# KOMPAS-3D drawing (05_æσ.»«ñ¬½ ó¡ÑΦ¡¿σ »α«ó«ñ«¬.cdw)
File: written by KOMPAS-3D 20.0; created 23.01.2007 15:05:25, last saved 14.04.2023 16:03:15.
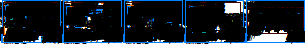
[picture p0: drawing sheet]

Sheets 1-5: A2, landscape

Document properties: Автор: Лескин; Организация: ЗАО ИТФ "СИСТЕМЫ И ТЕХНОЛОГИИ"; Разработал: Антошин; Проверил: Тарасов; Утвердил: Шмончев; Н. контр.: Силаков; Форматы листов документа: 5xA2; Полное имя файла: \\s-tech\depts\Отдел_ПКО\Проекты\Типовые проекты МКД 2023\!Типовой проект\1_Типовой проект МКД_RS-485\05_Сх.подкл внешних проводок.cdw

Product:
- Part/product: (unnamed)
  - Component: \\Helios\отдел_пко\Общая папка Компас\_Addons\Signatures\Signatures.lfr|Шмончев  | Полное имя файла: C:\Users\MAntoshin\AppData\Local\Temp\hsklda.frw; source file: \\s-tech\depts\Отдел_ПКО\Проекты\Program Files\ASCON\KOMPAS-3D V13\Libs\_Addons\Signatures\Signatures.lfr
  - Component: \\Helios\отдел_пко\Общая папка Компас\_Addons\Signatures\Signatures.lfr|Силаков  | Полное имя файла: C:\Users\MAntoshin\AppData\Local\Temp\eiczbt.frw; source file: \\s-tech\depts\Отдел_ПКО\Проекты\Program Files\ASCON\KOMPAS-3D V13\Libs\_Addons\Signatures\Signatures.lfr
  - Component: \\Helios\отдел_пко\Общая папка Компас\_Addons\Signatures\Signatures.lfr|Тарасов  | Полное имя файла: C:\Users\MAntoshin\AppData\Local\Temp\qlkzkl.frw; source file: \\s-tech\depts\Отдел_ПКО\Проекты\Program Files\ASCON\KOMPAS-3D V13\Libs\_Addons\Signatures\Signatures.lfr

Title block, sheet 1: designation: ВЛСТ 1277.01.002 С5; sheet number: 1; Количество листов документа: 3; organisation: АО ГК / "Системы и Технологии"; Форматы листов документа: A2; stored path: C:\Program Files\ASCON\KOMPAS-3D V8 Plus\Templates\Чертеж строительный зданий и сооружений.cdt; cell 302: Система учета электроэнергии (с организацией удаленного / сбора данных) потребителей; cell 303: Типовой проект ИСУЭ многоквартирного / дома с использованием проводного / канала связи RS-485; cell 304: Схема электрическая однолинейная; cell 320: Р
Title block, sheet 2: sheet number: 2; Форматы листов документа: A3; stored path: Z:\Проекты\ЭнергоКурган\СЭ_Схема однолинейная.cdw
Title block, sheet 3: sheet number: 3; Форматы листов документа: A4
Title block, sheet 4: sheet number: 4; stored path: \\s-tech\depts\Отдел_ПКО\Проекты\Типовые проекты МКД 2023\!Типовой проект\1_Типовой проект МКД_RS-485\ВНЕШН ПРОВОДКИ.cdw
Title block, sheet 5: sheet number: 5; designation, second copy: ВЛСТ 1277.01.002 С5-

Referenced files in \\Helios\отдел_пко\Общая папка Компас\_Addons\Signatures\: Signatures.lfr|Тарасов, Signatures.lfr, Signatures.lfr|Силаков, Signatures.lfr|Шмончев
Referenced files: qlkzkl.frw, eiczbt.frw, hsklda.frw
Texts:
  Тарасов
  Силаков
  Шмончев
  Normal
  Body Text,Письмо в Интернет,body text
  TXT
  Centerline
  Outline
  Питание
  COM1
  COM2
  COM3
  COM4
  RS-232
  ТС2-
  ТС+
  ТС1-
  GND
  ТxD
  RxD
  GSM
  Интеллектуальный контроллер
  SM160-02
  Ethernet
  МКД
  МY-Х-N
  Преобразователь линии
  Ethernet/RS-485
  (ВЛСТ 344.00.000-04)
  Этаж 1-5
  Этаж 6-10
  Этаж 11-15
  Этаж 16-17
  Подъезд 1
  Подъезд N
  Сч. Кв.1
  Сч. Кв.6
  Сч. Кв.2
  Сч. Кв.3
  Сч. Кв.4
  Сч. Кв.5
  Ethernet Port 1
  Коммутатор EDS-208
  Ethernet Port 2
  Ethernet Port 3
  Ethernet Port 4
  Ethernet Port 5
  Ethernet Port 6
  Ethernet Port 7
  Ethernet Port 8
  Электрощитовая №1
  МХ.N.6
  МХ.N.5
  МХ.N.4
  МХ.N.3
  МХ.N.2
  МХ.N.1
  Этаж 18
  Шкаф УСПД
  Клеммный блок для
  цепей RS-485
  ПРК
  ВЛСТ 215.00.000-04
  МY-Х-1(Р)
  Этаж 6
  Этаж 7-11
  ВРУ №2
  Сч. ОДПУ
  Сч. МОП
  ВРУ №1
  МY-Х-N(Р)
  АРК
  ВЛСТ 217.00.000-05
  Клеммник
  ("=24В для АРК")
  Этаж 1-8
  Этаж 9
  МN-2
  МN-3
  Этаж 1
  Этаж 2-4
  Этаж 5
  Подъезд 2
  интерфейса RS-485 для МКД до 5 этажей.
  Оборудование
  связи интернет
  провайдера
  (существующее)
  Антенна GSM
  МY-2
  МY-3
  Шина заземления
  На Этаж 12,
  В 1 подъезд,
  (см. лист  5)
  В N подъезд,
  В 2 подъезд,
  (не показано)
  В 3 подъезд,
  В Электрощитовую №1,
  Шкаф УСПД,
  на клеммный блок для
  (см. лист  4)
  МN.1.1
  МN.1.2
  МN.1.3
  МN.1.4
  МN.x.1
  МN.x.2
  МN.x.3
  МN.x.4
  МN.5.1
  МN.5.2
  МN.5.3
  МN.5.4
  МN-1
  МN-x
  МY-1
  В X подъезд,
  Вариант 1. Многоквартирный дом с этажностью - до 5
  Щит со счетчиками на площадке этажа, активная разветвительная коробка RS-485
  Вариант 2. Многоквартирный дом с этажностью - 9
  Два щита со счетчиками на площадке этажа, пассивная разветвительная коробка RS-485
  Вариант 3. Многоквартирный дом с этажностью - 14-18
  Вариант 4. Многоквартирный дом с этажностью - 14-18
  Щит со счетчиками на площадке этажа, пассивная разветвительная коробка RS-485 (начало)
  - однофазный счетчик КВАНТ ST1000-9;
  - трехфазный счетчик КВАНТ ST2000-12.
  Патч-корд
  UTP-RJ45-RJ45-5e-0,5M
  RS-485 для МКД до 9 этажей без применения АРК.
  может изменяться.
  RS-485 для МКД до 18 этажей с применением АРК.
  скруткой двух жил кабеля.
  RS-485 для МКД до 18 этажей без применения АРК.
  ПРК ранво 30 шт. При подключении более 30 счетчиков произвести смену пары (жилы кабеля)
  магистральной линии интерфейса RS-485 (см. схема внешних проводок ВЛСТ 1277.01.002 С5).
  - однофазный счетчик КВАНТ ST1000-9.
  Щит со счетчиками на площадке этажа, пассивная разветвительная коробка RS-485 (окончание)
  Преобразователь линии RS-485/CAN
  (ВЛСТ 217.00.000-04)
  CAN
  RS-485
  out
  POLYLINE_STYLE_0.09_RGB_0_0_0
  POLYLINE_STYLE_0.18_RGB_0_0_0
  POLYLINE_STYLE_0.09_RGB_0_0_255
  Черная основная
  Красная штриховая
  сплошная своя 0,54 мм на бумаге
  Красная основная
  CONTINUOUS0
  POLYLINE_STYLE_0.18_RGB_255_0_0
  CONTINUOUS_RGB_0_0_0_THICK_0.25
  Стили документа
  Разраб.
  Н.контр.
  Утв.
  Антошин
  Схема подключения внешних проводок
  03 Рабочие чертежи основного комплекта. ГОСТ Р 21.1101-2009 Ф3
  05 Чертежи строительных изделий. Посл. листы. ГОСТ Р 21.1101-2009 Ф6
Dimensions and other numbers on the sheet: 1,8; 2,5; 1; 2; 3; 4; 5; 6; +10..30 В; -10..30 В; 8; 7; 9; 10; 11; 12; 1   2  3; +10...30 В; 4  5  6; -10...30 В; 1.1.1; 4.1.1; 1.1.2; 1.2.1; 1.2.2; 1.3.1; 1.3.2; 1.4.1; 1.4.2; 2.1.1; 2.1.2; 2.2.1; 2.2.2; 2.3.1; 2.3.2; 2.4.1; 2.4.2; 3.1.1; 3.1.2; 3.2.1; 3.2.2; 3.3.1; 3.3.2; 3.4.1; 3.4.2; 4.1.2; 4.2.1; 4.2.2; 4.3.1; 4.3.2; 4.4.1; 4.4.2; 5.1; 5.2; 6.1; 6.2; 3-6; 1.1; 1.2; 2.1; 2.2; 3.1; 3.2; 3.3; 3.4; 1.10; 2.10; 3.10; 6.10; 5.10; 1.4..10; 1.3.10; 1.2.10; 1.1.10; 1.4.10; 4.10; 2 этаж, ПРК; 1 этаж, АРК; 1 этаж, ПРК; 4  5   6; 5 В; 100 мА; 24; 25; 10.21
